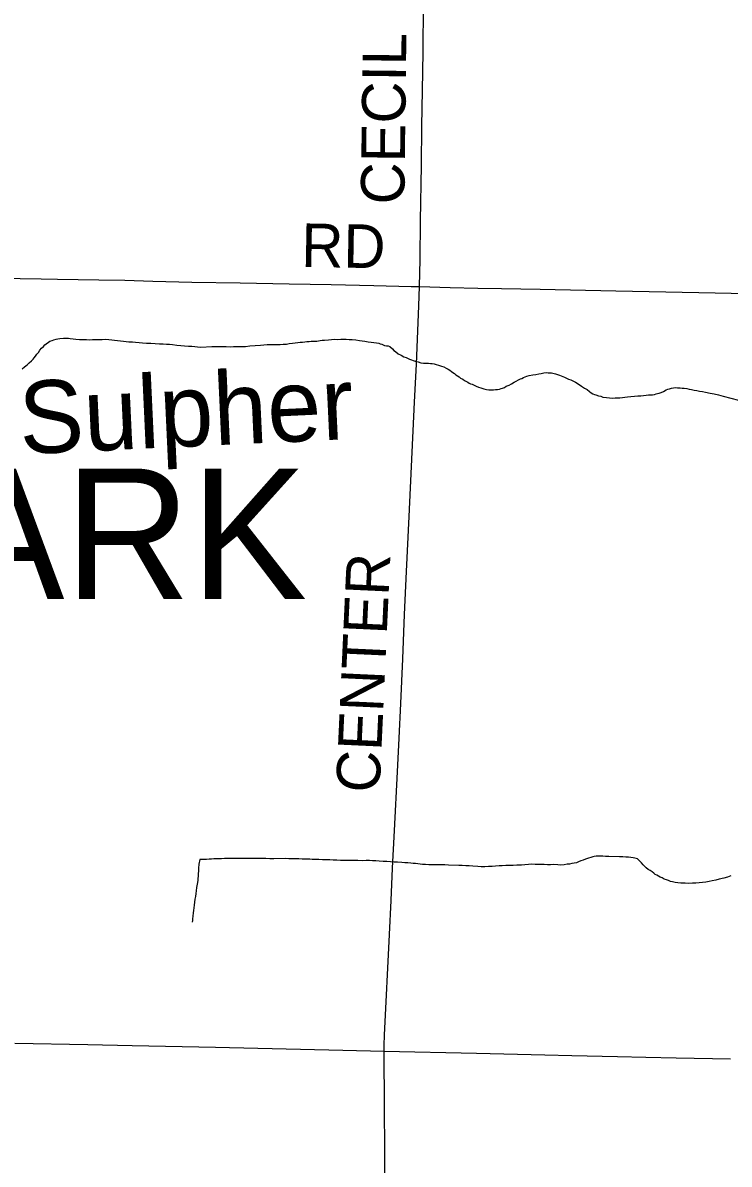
# Model space of a CAD drawing. Extents: x 2.1 to 73.9, y 4 to 26.
# Drawn here: x 42.405 to 42.866, y 23.321 to 24.066 of the extents above; entities that cross this region are included whole.
import ezdxf

# ---------------------------------------------------------------- set-up
doc = ezdxf.new("R2010")
doc.units = 0
for name, color, linetype in [('GM_X_Minor_River', 7, 'Continuous'), ('GM_X_Minor_River_Text', 7, 'Continuous'), ('GM_X_State_Route', 7, 'Continuous'), ('GM_X_Township_Road', 7, 'Continuous'), ('GM_X_Township_Road_Text', 7, 'Continuous'), ('GM_X_Township_Text', 7, 'Continuous')]:
    doc.layers.add(name, color=color, linetype=linetype)

msp = doc.modelspace()

# ---------------------------------------------------------------- linework, layer by layer
at = {"layer": 'GM_X_Minor_River'}
for points in [[(42.40489, 23.83971), (42.40643, 23.8412), (42.40817, 23.8425), (42.40952, 23.84362), (42.41106, 23.84512), (42.41203, 23.84605), (42.4128, 23.84699), (42.41358, 23.84812), (42.41455, 23.84943), (42.41552, 23.85055), (42.4165, 23.85206), (42.41766, 23.85337), (42.41882, 23.85449), (42.41978, 23.85542), (42.42306, 23.85784), (42.42459, 23.85839), (42.42555, 23.85875), (42.42707, 23.85911), (42.42822, 23.85928), (42.42955, 23.85964), (42.43184, 23.85979), (42.43355, 23.85976), (42.43507, 23.85974), (42.43621, 23.85953), (42.43811, 23.85931), (42.44, 23.85909), (42.44229, 23.85905), (42.44457, 23.85902), (42.44685, 23.85898), (42.44913, 23.85876), (42.45084, 23.85892), (42.45236, 23.85889), (42.45484, 23.85905), (42.45712, 23.85901), (42.45941, 23.85916), (42.46149, 23.85894), (42.46339, 23.85872), (42.4651, 23.8585), (42.46719, 23.85828), (42.46909, 23.85806), (42.47099, 23.85784), (42.47269, 23.85762), (42.47459, 23.8574), (42.47687, 23.85737), (42.47896, 23.85714), (42.48124, 23.85692), (42.48352, 23.85688), (42.48599, 23.85665), (42.48884, 23.85661), (42.49169, 23.85637), (42.49454, 23.85614)], [(42.49454, 23.85614), (42.49701, 23.8561), (42.4991, 23.85587), (42.501, 23.85584), (42.5029, 23.85562), (42.50575, 23.8552), (42.50841, 23.85497), (42.51088, 23.85474), (42.51354, 23.85469), (42.51563, 23.85466), (42.51753, 23.85444), (42.51924, 23.85422), (42.52151, 23.854), (42.52875, 23.85445), (42.53236, 23.8544), (42.53521, 23.85435), (42.53807, 23.8543), (42.54073, 23.85426), (42.54282, 23.85442), (42.54472, 23.85439), (42.54644, 23.85436), (42.54834, 23.85433), (42.55062, 23.85449), (42.55348, 23.85482), (42.55691, 23.85496), (42.56033, 23.85528), (42.56471, 23.85559), (42.56757, 23.85574), (42.57061, 23.85569), (42.57327, 23.85564), (42.57518, 23.8558), (42.57727, 23.85596), (42.57918, 23.85631), (42.58127, 23.85647), (42.58299, 23.85682), (42.58471, 23.85698), (42.58623, 23.85715), (42.58775, 23.85731), (42.58928, 23.85748), (42.59061, 23.85765), (42.59213, 23.85762), (42.59347, 23.85779), (42.5948, 23.85777), (42.59594, 23.85794), (42.59708, 23.85793), (42.59823, 23.8581), (42.59937, 23.85827), (42.60071, 23.85844), (42.60223, 23.8586), (42.6047, 23.85875), (42.6068, 23.85891), (42.60889, 23.85907), (42.6108, 23.85904), (42.6127, 23.8592), (42.6146, 23.85917), (42.61631, 23.85914), (42.61821, 23.85892), (42.6203, 23.85889), (42.62258, 23.85866), (42.62505, 23.85824), (42.62846, 23.85781), (42.63074, 23.85739), (42.63264, 23.85717), (42.63605, 23.85674), (42.63757, 23.85652), (42.63852, 23.85613), (42.63946, 23.85592), (42.64041, 23.85553), (42.64135, 23.85513), (42.64268, 23.85492), (42.64363, 23.85472), (42.64476, 23.85432), (42.64645, 23.85277), (42.64739, 23.85181), (42.64852, 23.85103), (42.6502, 23.84968), (42.65209, 23.8487), (42.65398, 23.84772), (42.65549, 23.84712), (42.65662, 23.84653), (42.65757, 23.84614), (42.66135, 23.84475), (42.66324, 23.84434), (42.66494, 23.84374), (42.66665, 23.84353), (42.66798, 23.84351), (42.66894, 23.84349), (42.67008, 23.84347), (42.67121, 23.84326), (42.67235, 23.84325), (42.67368, 23.84303), (42.67501, 23.84263), (42.67652, 23.84223), (42.67841, 23.84163), (42.67993, 23.84104), (42.68144, 23.84025), (42.68276, 23.83966), (42.68389, 23.83888), (42.68501, 23.83811), (42.68596, 23.83752), (42.68689, 23.83675)], [(42.68689, 23.83675), (42.68783, 23.83597), (42.68896, 23.8352), (42.6899, 23.83461), (42.69084, 23.83365), (42.69235, 23.83305), (42.69348, 23.83228), (42.69442, 23.83169), (42.69555, 23.8311), (42.69649, 23.83052), (42.69744, 23.83012), (42.69838, 23.82973), (42.69971, 23.82914), (42.70103, 23.82855), (42.70254, 23.82795), (42.70405, 23.82736), (42.70613, 23.82676), (42.70784, 23.82635), (42.70936, 23.82614), (42.71088, 23.82611), (42.7124, 23.82609), (42.71373, 23.82626), (42.71507, 23.82643), (42.7164, 23.82659), (42.71736, 23.82696), (42.71831, 23.82713), (42.71946, 23.82768), (42.72062, 23.82843), (42.72253, 23.82916), (42.72407, 23.83008), (42.72579, 23.831), (42.73001, 23.83321), (42.73097, 23.83358), (42.73193, 23.83413), (42.73403, 23.83505), (42.73575, 23.8354), (42.73804, 23.83593), (42.73995, 23.83609), (42.74185, 23.83644), (42.74357, 23.8368), (42.74529, 23.83715), (42.74681, 23.83732), (42.74815, 23.83729), (42.74929, 23.83728), (42.75024, 23.83726), (42.75194, 23.83685), (42.75289, 23.83646), (42.75421, 23.83606), (42.75535, 23.83566), (42.75648, 23.83526), (42.75762, 23.83486), (42.75875, 23.83428), (42.76007, 23.83369), (42.76139, 23.83309), (42.76272, 23.83269), (42.76423, 23.83191), (42.76592, 23.83112), (42.76762, 23.82996), (42.76988, 23.82859), (42.77176, 23.82723), (42.77345, 23.82626), (42.77496, 23.82509), (42.77608, 23.82412), (42.77721, 23.82354), (42.77816, 23.82314), (42.77911, 23.82294), (42.78081, 23.82215), (42.78232, 23.82194), (42.78364, 23.82135), (42.78611, 23.82112), (42.78801, 23.8209), (42.7901, 23.82067), (42.79182, 23.82084), (42.79334, 23.82081), (42.79486, 23.82098), (42.79658, 23.82114), (42.7981, 23.82131), (42.79981, 23.82147), (42.80648, 23.82212), (42.80858, 23.82228), (42.81029, 23.82244), (42.812, 23.8226), (42.81353, 23.82277), (42.81505, 23.82293), (42.81619, 23.82292), (42.81734, 23.82309), (42.81848, 23.82345), (42.81944, 23.82381), (42.82039, 23.82399), (42.82173, 23.82435), (42.82326, 23.82508), (42.82499, 23.8262), (42.82614, 23.82656), (42.82729, 23.82673), (42.82843, 23.82709), (42.82977, 23.82745), (42.8311, 23.82762), (42.83243, 23.82741), (42.83414, 23.82738), (42.83547, 23.82717), (42.8368, 23.82715)], [(42.8368, 23.82715), (42.83851, 23.82693), (42.84003, 23.82653), (42.84154, 23.82631), (42.84325, 23.82591), (42.84496, 23.82569), (42.84666, 23.82528), (42.84875, 23.82506), (42.85065, 23.82465), (42.85368, 23.82403), (42.85633, 23.82342), (42.85917, 23.8228), (42.86221, 23.822), (42.87224, 23.81937)], [(42.82238, 23.50754), (42.82105, 23.50813), (42.81992, 23.50871), (42.81898, 23.5093), (42.81785, 23.50989), (42.81691, 23.51066), (42.81598, 23.51163), (42.81466, 23.51241), (42.81334, 23.51319), (42.81202, 23.51416), (42.8109, 23.51532), (42.80996, 23.51609), (42.80884, 23.51744), (42.80753, 23.51879), (42.80622, 23.51995), (42.80451, 23.52055), (42.80338, 23.52075), (42.80205, 23.52097), (42.80034, 23.52118), (42.79863, 23.52121), (42.79673, 23.52143), (42.79464, 23.52146), (42.7876, 23.52158), (42.78551, 23.52161), (42.7838, 23.52183), (42.7819, 23.52186), (42.78057, 23.52188), (42.77943, 23.52171), (42.77809, 23.52154), (42.77714, 23.52136), (42.7758, 23.521), (42.77446, 23.52045), (42.77236, 23.51973), (42.77083, 23.51918), (42.7693, 23.51864), (42.76777, 23.51809), (42.76643, 23.51754), (42.76509, 23.51719), (42.76357, 23.51702), (42.76204, 23.51666), (42.76033, 23.5165), (42.75842, 23.51615), (42.75632, 23.516), (42.75442, 23.51603), (42.75157, 23.51626), (42.74967, 23.5161), (42.74758, 23.51613), (42.74549, 23.51636), (42.7434, 23.51639), (42.74149, 23.51642), (42.73959, 23.51645), (42.73731, 23.51649), (42.73522, 23.51633), (42.73293, 23.51618), (42.73065, 23.51602), (42.7276, 23.51588), (42.72513, 23.51573), (42.72266, 23.51577), (42.72037, 23.51562), (42.71809, 23.51546), (42.71599, 23.5155), (42.71371, 23.51534), (42.71142, 23.515), (42.70914, 23.51504), (42.70667, 23.51489), (42.70438, 23.51492), (42.7021, 23.51515), (42.69887, 23.5152), (42.69659, 23.51543), (42.69431, 23.51546), (42.69203, 23.51569), (42.68975, 23.51572), (42.6831, 23.51602), (42.68063, 23.51606), (42.67797, 23.5161), (42.67549, 23.51614), (42.67245, 23.51619), (42.67017, 23.51623), (42.66808, 23.51626), (42.66618, 23.51629), (42.66447, 23.51651), (42.66295, 23.51672), (42.66143, 23.51693), (42.65991, 23.51696), (42.65839, 23.51717), (42.65649, 23.51739), (42.65459, 23.51742), (42.6525, 23.51765), (42.64966, 23.51788), (42.64756, 23.51791), (42.6451, 23.51814), (42.64282, 23.51837), (42.64034, 23.51822), (42.63787, 23.51845), (42.63559, 23.51868), (42.6335, 23.51871), (42.63141, 23.51893), (42.62932, 23.51896), (42.62704, 23.51881), (42.6238, 23.51886), (42.62152, 23.5189)], [(42.62152, 23.5189), (42.61924, 23.51893), (42.61696, 23.51897), (42.61487, 23.519), (42.61259, 23.51904), (42.6103, 23.51908), (42.60783, 23.51912), (42.60555, 23.51934), (42.60308, 23.51938), (42.6008, 23.51942), (42.59852, 23.51964), (42.59605, 23.51968), (42.59415, 23.51971), (42.59263, 23.51974), (42.59111, 23.51976), (42.58921, 23.51979), (42.58749, 23.51982), (42.58541, 23.52004), (42.58331, 23.52007), (42.58122, 23.52011), (42.57894, 23.52014), (42.57685, 23.52018), (42.56905, 23.52011), (42.56658, 23.52015), (42.56392, 23.52019), (42.56125, 23.52024), (42.55878, 23.52028), (42.55593, 23.52032), (42.55327, 23.52036), (42.5506, 23.52021), (42.54794, 23.52026), (42.54547, 23.5203), (42.54281, 23.52034), (42.5409, 23.52018), (42.53881, 23.52021), (42.53691, 23.52024), (42.535, 23.52008), (42.53329, 23.52011), (42.53139, 23.51995), (42.52987, 23.51997), (42.52834, 23.51981), (42.52682, 23.51983), (42.52511, 23.51967), (42.52244, 23.51952), (42.52092, 23.51955), (42.52011, 23.51652), (42.52007, 23.51386), (42.52005, 23.51253), (42.51982, 23.51007), (42.51956, 23.50589), (42.51914, 23.50343), (42.51873, 23.50135), (42.51851, 23.49926), (42.51829, 23.49736), (42.51807, 23.49547), (42.51766, 23.49376), (42.51744, 23.49168), (42.51703, 23.48978), (42.517, 23.48808), (42.51678, 23.48637), (42.51657, 23.48485), (42.51634, 23.48258), (42.51612, 23.48087), (42.51611, 23.47973), (42.5159, 23.47878), (42.5159, 23.47878)], [(42.86709, 23.50891), (42.86499, 23.50819), (42.8627, 23.50746), (42.85964, 23.50675), (42.85735, 23.50622), (42.85506, 23.50569), (42.85296, 23.50534), (42.85086, 23.5048), (42.84877, 23.50465), (42.84648, 23.5043), (42.84439, 23.50415), (42.8421, 23.50418), (42.83982, 23.50403), (42.83735, 23.50407), (42.83468, 23.50411), (42.8326, 23.50433), (42.83089, 23.50455), (42.82918, 23.50496), (42.82786, 23.50536), (42.82653, 23.50595), (42.82521, 23.50635), (42.82369, 23.50675), (42.82238, 23.50754)]]:
    msp.add_lwpolyline(points, dxfattribs=at)
at = {"layer": 'GM_X_State_Route'}
msp.add_lwpolyline([(42.40023, 23.39986), (42.44778, 23.39887), (42.47668, 23.39821), (42.53107, 23.39708), (42.61405, 23.39522), (42.64106, 23.3946), (42.70138, 23.39323), (42.74582, 23.39208), (42.76353, 23.39174), (42.79337, 23.39108), (42.8117, 23.39067), (42.8316, 23.39014), (42.86702, 23.38944)], dxfattribs=at)
at = {"layer": 'GM_X_Township_Road'}
for points in [[(42.66417, 23.89354), (42.66448, 23.91117), (42.66482, 23.93635), (42.66544, 23.9724), (42.66574, 23.99819), (42.66606, 24.0215), (42.66646, 24.04637), (42.66681, 24.07776), (42.66731, 24.11412), (42.6675, 24.14334), (42.66811, 24.17939), (42.66869, 24.2027), (42.66918, 24.22072), (42.66954, 24.2347), (42.67017, 24.25738), (42.67092, 24.28006), (42.67188, 24.3074), (42.67343, 24.35773), (42.67417, 24.37854), (42.67456, 24.39159), (42.67475, 24.39777)], [(42.14928, 23.90369), (42.1517, 23.90365), (42.17874, 23.90317), (42.20702, 23.90269), (42.24246, 23.90208), (42.30119, 23.90085), (42.31052, 23.90068), (42.33445, 23.90009), (42.34719, 23.89986), (42.38977, 23.89904), (42.41743, 23.89851), (42.428, 23.89835), (42.45504, 23.89784), (42.47183, 23.89762), (42.49016, 23.89708), (42.51564, 23.8964), (42.54704, 23.89597), (42.57905, 23.8953), (42.6064, 23.89477), (42.63437, 23.89425), (42.65861, 23.89362), (42.66417, 23.89354)], [(42.64106, 23.3946), (42.64115, 23.39854), (42.64139, 23.40506), (42.64451, 23.47057), (42.64554, 23.49293), (42.64657, 23.51404), (42.64779, 23.53856), (42.64974, 23.57675), (42.65094, 23.59878), (42.65191, 23.62145), (42.65315, 23.65064), (42.65437, 23.67952), (42.65565, 23.70747), (42.6573, 23.74349), (42.66084, 23.818), (42.66207, 23.84284), (42.66373, 23.88103), (42.66417, 23.89354)], [(42.66417, 23.89354), (42.68409, 23.89296), (42.70211, 23.89246), (42.71766, 23.89225), (42.74283, 23.89182), (42.79225, 23.89072), (42.814, 23.89023), (42.84633, 23.88971), (42.87803, 23.88897), (42.90942, 23.88829), (42.93055, 23.88777), (42.95852, 23.88706), (42.97624, 23.88673), (43.00856, 23.88618), (43.02969, 23.88566), (43.06544, 23.88498), (43.09807, 23.88432), (43.13133, 23.88372), (43.15369, 23.88288), (43.15705, 23.88275)], [(42.64303, 23.13786), (42.64298, 23.15207), (42.64287, 23.17662), (42.64239, 23.23226), (42.6419, 23.28354), (42.6415, 23.32208), (42.64123, 23.3656), (42.64104, 23.38673), (42.64106, 23.3946)]]:
    msp.add_lwpolyline(points, dxfattribs=at)

# ---------------------------------------------------------------- texts
at = {"layer": 'GM_X_Minor_River_Text'}
msp.add_text('Sulpher', height=0.047375, rotation=2.64866, dxfattribs=at).set_placement((42.40386, 23.78405))
at = {"layer": 'GM_X_Township_Road_Text'}
for s, rotation, p in [('CECIL', 89.28986, (42.6542, 23.94695)), ('RD', 359.0023, (42.58683, 23.90634)), ('CENTER', 87.34916, (42.63796, 23.56279))]:
    msp.add_text(s, height=0.028409, rotation=rotation, dxfattribs=at).set_placement(p)
at = {"layer": 'GM_X_Township_Text'}
msp.add_text('MARK', height=0.085227, rotation=0.00001, dxfattribs=at).set_placement((42.26162, 23.68953))

doc.saveas('drawing.dxf')
